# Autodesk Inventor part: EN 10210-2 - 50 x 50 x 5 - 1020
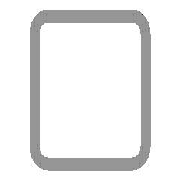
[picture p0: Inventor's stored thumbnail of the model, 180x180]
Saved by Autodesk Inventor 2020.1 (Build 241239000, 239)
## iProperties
IsCustomPart: 1
_CCFamilyMember: 16
_CCFamilyDisplayName: DIN EN 10210-2 (USAS B17.1 quadratisch) - Rohrleitung — In Klammern angegebene Größen wurden aufgehoben
_FrameMemberDoc: Frame Member File
_Version: 15.0.0
_GetPNFromCC: 1
Created: 2019-01
Part Number: EN 10210-2 - 50 x 50 x 5 - 1020
Material: Stahl, weich
Description: Rohrleitung
Document SubType Name: Modeling
Standard: DIN
Designer: lutzd
Standard Revision: 2006-07
Standards Organization: DIN
Language: de-DE
Size Designation: 50 x 50 x 5
Categories: <MemberInstance><Categories><Category DisplayName="Profile" InternalName="089c4875-fa83-4c05-b084-43b9cc11f5ed" Mnemonic="GRDR"><CategoryParameter DisplayName="
Stock Number: 50 x 50 x 5
Mass: 6986.06 g
Surface Area: 3471.97 cm^2
Volume: 889.944 cm^3
Density: 7.85 g/cm^3
Appearance: Semi-Polished(8)
G_L: 1020,000 mm
G_W: 50,000 mm
G_H: 50,000 mm
DocNumber: ADSK-014271
Folder: .
Dimensions: 50x50x1020 mm
Mass: 6,986 kg
VLT_Material: Stahl, weich
Title: Profil-Bauteil
Author: lutzd
Revision Number: -
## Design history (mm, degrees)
node "Startebene"
node "Endebene"
sketch "Skizze"
  geometry: L1 (-25, -17.5)-(-25, 17.5); L2 (-17.5, 25)-(17.5, 25); L3 (25, 17.5)-(25, -17.5); L4 (17.5, -25)-(-17.5, -25); L5 (-15, 20)-(15, 20); L6 (20, 15)-(20, -15); L7 (15, -20)-(-15, -20); L8 (-20, -15)-(-20, 15); L9 (0, 37.175)-(0, -37.175) reference; L10 (-37.175, 0)-(37.175, 0) reference; A1 r 7.5 centre (-17.5, -17.5) between (-25, -17.5) and (-17.5, -25); A2 r 7.5 centre (-17.5, 17.5) between (-17.5, 25) and (-25, 17.5); A3 r 7.5 centre (17.5, 17.5) between (25, 17.5) and (17.5, 25); A4 r 7.5 centre (17.5, -17.5) between (17.5, -25) and (25, -17.5); A5 r 5 centre (-15, -15) between (-20, -15) and (-15, -20); A6 r 5 centre (-15, 15) between (-15, 20) and (-20, 15); A7 r 5 centre (15, 15) between (20, 15) and (15, 20); A8 r 5 centre (15, -15) between (15, -20) and (20, -15)
  constraints: 16 end point, 16 point on circle, 16 tangent, 8 centre point, 6 equal radius, 4 parallel, 2 perpendicular, 2 other
  dimensions: "d7" = 7.5 radius of A1 (= G_IR); "d10" = 50 distance between parallel lines of L2 L4 (= G_H); "d11" = 50 distance between parallel lines of L1 L3 (= G_W); "d12" = 5 distance between parallel lines of L3 L6 (= G_T); "d15" = 25 distance between parallel lines of L2 L10 (= 0.5 x d10); "d16" = 25 distance between parallel lines of L9 L3 (= 0.5 x d11); "d19" = 5 radius of A5 (= G_T); "d20" = 5 distance between parallel lines of L4 L7 (= G_T)
extrude "Körper" new body sketch "Skizze" stored distance "d3" = 1020 (= G_L); taper "d4" = 0 deg
node "Driven Length"
  sketch "Sketch3"
    geometry: L1 (0, 0)-(10, 0) reference
    constraints: 2 end point, 1 horizontal
  workplane "Work Plane3"
  sketch "Sketch4"
    geometry: L1 (-2, 0)-(12, 0) reference; L2 (-2, 1020)-(12, 1020) reference
    dimensions: "d18" = 1020 distance between parallel lines of L1 L2 (derived)
sketch "Skizze5"
  geometry: L1 (0, 35)-(0, 0) reference; L2 (0, 17.5)-(430.5, 17.5); 3 further points
  constraints: 2 end point, 1 coincident, 1 horizontal, 1 midpoint, 1 point on line
  dimensions: "d21" = 51 distance of point (430.5, 17.5) point (379.5, 17.5); "d23" = 379.5 distance of L2.start point (379.5, 17.5)
hole "Bohrung1" sketch "Skizze5" at (430.5, 17.5), (379.5, 17.5) diameter "d24" = 6.647; stored, may be unused: countersink angle "d28" = 90 deg, drill point angle "d30" = 118 deg; dims "d25" = 16, "d26" = 17.3, "d27" = 2, "d29" = 22.2
sketch "Skizze6"
  geometry: L1 (35, 0)-(0, 0) reference; L2 (17.5, 0)-(17.5, 691.5); 2 further points
  constraints: 2 end point, 1 coincident, 1 point on line, 1 vertical
  dimensions: "d31" = 153 distance of point (17.5, 691.5) point (17.5, 538.5); "d32" = 538.5 distance from line of L1 point (17.5, 538.5)
hole "Bohrung2" sketch "Skizze6" at (17.5, 691.5), (17.5, 538.5) diameter "d33" = 6.647; stored, may be unused: countersink angle "d37" = 90 deg, drill point angle "d39" = 118 deg; dims "d34" = 16, "d35" = 17.3, "d36" = 2, "d38" = 22.2
body "Solid1"
other parameters: "G_W" = 50 [user parameter; used in 1 equation term], "G_H" = 50 [user parameter; used in 1 equation term], "G_T" = 5 [user parameter; used in 3 equation terms], "G_IR" = 7.5 [user parameter; used in 1 equation term], "G_L" = 1020 (= d18) [user parameter; used in 1 equation term], "G_OFFSET_START" = 0 [user parameter; used in 1 equation term], "G_OFFSET_END" = 0 [user parameter; used in 1 equation term], "d13" = 0 (computed from G_OFFSET_START), "d17" = 90 deg
